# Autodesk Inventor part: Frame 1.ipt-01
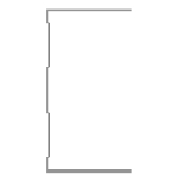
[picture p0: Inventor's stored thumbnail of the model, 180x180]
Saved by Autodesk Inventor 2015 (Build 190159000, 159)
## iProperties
IsCustomPart: 1
Created: 2015-04
Part Number: Frame 1.ipt-01
Material: Aluminum 6061
Description: Kévin Novo
Document SubType Name: Modeling
Standard: Kevin
Designer: suporte
Standards Organization: Kevin
Language: en-US
Size Designation: (Unnamed 1)
Categories: <MemberInstance><Categories><Category DisplayName="Structural Shapes" InternalName="089c4875-fa83-4c05-b084-43b9cc11f5ed" Mnemonic="GRDR"><CategoryParameter Dis
Density: 2.7 g/cm^3
Appearance: Aluminum - Flat
_CCFamilyMember: 1
_CCFamilyDisplayName: Kévin - Kévin Novo
_FrameMemberDoc: Frame Member File
_Version: 15.0.0
_GetPNFromCC: 1
G_L: 217,500 mm
G_W: 50,000 mm
G_H: 75,000 mm
+084733DE-06F5-4E36-B81D-E3E7BB255A96+CUTDETAIL1: Cut
Author: suporte
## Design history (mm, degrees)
node "Start Plane"
node "End Plane"
sketch "Sketch"
  geometry: L1 (24.7, 37.5)-(24.7, 36.9); L2 (24.7, 36.9)-(-24.7, 36.9); L3 (-24.7, -36.9)-(24.7, -36.9); L4 (24.7, -36.9)-(24.7, -37.5); L5 (24.7, -37.5)-(-25.3, -37.5); L6 (-25.3, 37.5)-(24.7, 37.5); L7 (-24.7, 36.9)-(-24.7, 31.9); L8 (-24.7, 31.9)-(-23.3, 30.5); L9 (-23.3, 30.5)-(-23.3, 10.934); L10 (-23.3, 10.934)-(-24.7, 9.534); L11 (-24.7, 9.534)-(-24.7, -9.534); L12 (-24.7, -9.534)-(-23.3, -10.934); L13 (-23.3, -10.934)-(-23.3, -30.5); L14 (-23.3, -30.5)-(-24.7, -31.9); L15 (-24.7, -31.9)-(-24.7, -36.9); L16 (-25.3, -37.5)-(-25.3, -31.651); L17 (-25.3, -31.651)-(-23.9, -30.251); L18 (-23.9, -30.251)-(-23.9, -11.183); L19 (-23.9, -11.183)-(-25.3, -9.783); L20 (-25.3, -9.783)-(-25.3, 9.783); L21 (-25.3, 9.783)-(-23.9, 11.183); L22 (-23.9, 11.183)-(-23.9, 30.251); L23 (-23.9, 30.251)-(-25.3, 31.651); L24 (-25.3, 31.651)-(-25.3, 37.5); L25 (-25.3, 0)-(30.37, 0); 3 further points
  constraints: 50 end point, 10 point on line, 9 parallel, 5 perpendicular, 4 equal length, 3 midpoint, 3 vertical, 2 vertical alignment, 1 collinear, 1 horizontal, 1 horizontal alignment
  dimensions: "d3" = 0.6 distance of L1.start L1.end (= d6); "d5" = 75 distance between parallel lines of L5 L6; "d6" = 0.6 distance between parallel lines of L24 L7 (= d8); "d7" = 0.6 distance between parallel lines of L8 L23 (= d8); "d8" = 0.6 distance between parallel lines of L22 L9 (= d12); "Espessura" = 0.6 distance between parallel lines of L17 L14; "d10" = 0.6 distance between parallel lines of L13 L18 (= Espessura); "d11" = 0.6 distance between parallel lines of L12 L19 (= Espessura); "d12" = 0.6 distance between parallel lines of L21 L10 (= d11); "d13" = 5 distance of L2.end L7.end; "d15" = 135 deg angle of L9 L8; "d16" = 2 distance between parallel lines of L24 L9; "d17" = 50 distance of L6.start L1.start
extrude "Body" join sketch "Sketch" stored distance "d24" = 0.13; taper "d25" = 0 deg
node "Driven Length"
  sketch "Sketch10"
    geometry: L1 (0, 0)-(10, 0) reference
    constraints: 2 end point, 1 horizontal
  workplane "Work Plane7"
  sketch "Sketch11"
    geometry: L1 (-2, 0)-(12, 0) reference; L2 (-2, 217.5)-(12, 217.5) reference
    dimensions: "d27" = 217.5 distance between parallel lines of L1 L2 (derived)
workplane "Work Plane8"
split "Split1"
body "Solid1"
other parameters: "G_OFFSET_START" = 0 [user parameter; used in 1 equation term], "G_OFFSET_END" = -12.5 [user parameter; used in 1 equation term], "d22" = 0 (computed from G_OFFSET_START), "d23" = 217.5 (= tamanho + G_OFFSET_END), "G_L" = 217.5 (= d27) [user parameter], "d34" = 90 deg
